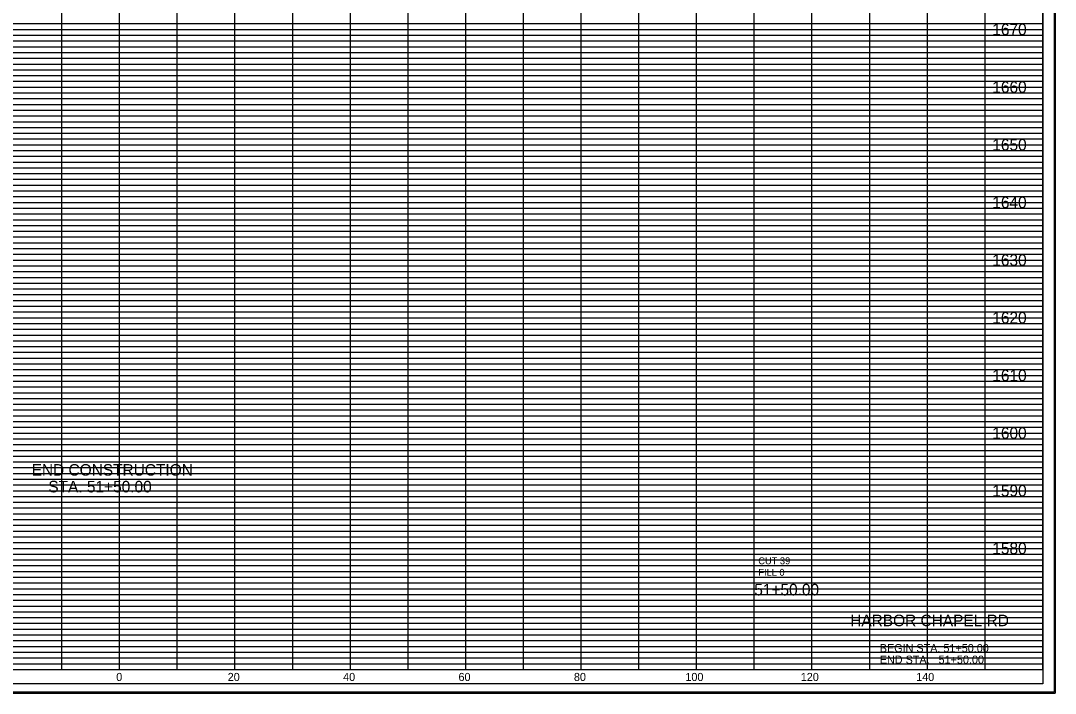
# Model space of a CAD drawing. Extents: x 980 to 1324, y 978 to 1767.
# Drawn here: x 1142.9 to 1322.2, y 1265.9 to 1382.5 of the extents above; entities that cross this region are included whole.
import ezdxf

# ---------------------------------------------------------------- set-up
doc = ezdxf.new("R2010")
doc.units = 0
for name, color, linetype in [('DESIGN - SHEET - Corner Text', 7, 'Continuous'), ('DESIGN - SHEET - Light Grid', 7, 'Continuous'), ('DESIGN - SHEET - Linework', 7, 'Continuous'), ('DESIGN - SHEET - Plot Shape', 7, 'Continuous'), ('DESIGN - TYPICAL - Finished Grade and Subgrade', 7, 'Continuous'), ('DESIGN - TYPICAL - Text', 7, 'Continuous')]:
    doc.layers.add(name, color=color, linetype=linetype)

# ---------------------------------------------------------------- blocks, each defined once
blk = doc.blocks.new('XSTSHT')
at = {"layer": 'DESIGN - SHEET - Light Grid'}
for p, q in [((8, 11.2), (16, 11.2)), ((16, 11.2), (24, 11.2)), ((24, 11.2), (32, 11.2)), ((8, 11.1), (16, 11.1)), ((16, 11.1), (24, 11.1)), ((24, 11.1), (32, 11.1)), ((8, 10.9), (16, 10.9)), ((8, 10.8), (16, 10.8)), ((16, 10.9), (24, 10.9)), ((16, 10.8), (24, 10.8)), ((24, 10.9), (32, 10.9)), ((24, 10.8), (32, 10.8)), ((8, 10.7), (16, 10.7)), ((8, 10.6), (16, 10.6)), ((16, 10.7), (24, 10.7)), ((16, 10.6), (24, 10.6)), ((24, 10.7), (32, 10.7)), ((24, 10.6), (32, 10.6)), ((8, 10.5), (16, 10.5)), ((8, 10.4), (16, 10.4)), ((16, 10.5), (24, 10.5)), ((16, 10.4), (24, 10.4)), ((24, 10.5), (32, 10.5)), ((24, 10.4), (32, 10.4)), ((8, 10.3), (16, 10.3)), ((16, 10.3), (24, 10.3)), ((24, 10.3), (32, 10.3)), ((8, 10.2), (16, 10.2)), ((8, 10.1), (16, 10.1)), ((16, 10.2), (24, 10.2)), ((16, 10.1), (24, 10.1)), ((24, 10.2), (32, 10.2)), ((24, 10.1), (32, 10.1)), ((8, 9.9), (16, 9.9)), ((16, 9.9), (24, 9.9)), ((24, 9.9), (32, 9.9)), ((8, 9.8), (16, 9.8)), ((8, 9.7), (16, 9.7)), ((16, 9.8), (24, 9.8)), ((16, 9.7), (24, 9.7)), ((24, 9.8), (32, 9.8)), ((24, 9.7), (32, 9.7)), ((8, 9.6), (16, 9.6)), ((16, 9.6), (24, 9.6)), ((24, 9.6), (32, 9.6)), ((8, 9.5), (16, 9.5)), ((8, 9.4), (16, 9.4)), ((16, 9.5), (24, 9.5)), ((16, 9.4), (24, 9.4)), ((24, 9.5), (32, 9.5)), ((24, 9.4), (32, 9.4)), ((8, 9.3), (16, 9.3)), ((8, 9.2), (16, 9.2)), ((16, 9.3), (24, 9.3)), ((16, 9.2), (24, 9.2)), ((24, 9.3), (32, 9.3)), ((24, 9.2), (32, 9.2)), ((8, 9.1), (16, 9.1)), ((16, 9.1), (24, 9.1)), ((24, 9.1), (32, 9.1)), ((8, 8.9), (16, 8.9)), ((8, 8.8), (16, 8.8)), ((16, 8.9), (24, 8.9)), ((16, 8.8), (24, 8.8)), ((24, 8.9), (32, 8.9)), ((24, 8.8), (32, 8.8)), ((8, 8.7), (16, 8.7)), ((16, 8.7), (24, 8.7)), ((24, 8.7), (32, 8.7)), ((8, 8.6), (16, 8.6)), ((8, 8.5), (16, 8.5)), ((16, 8.6), (24, 8.6)), ((16, 8.5), (24, 8.5)), ((24, 8.6), (32, 8.6)), ((24, 8.5), (32, 8.5)), ((8, 8.4), (16, 8.4)), ((8, 8.3), (16, 8.3)), ((16, 8.4), (24, 8.4)), ((16, 8.3), (24, 8.3)), ((24, 8.4), (32, 8.4)), ((24, 8.3), (32, 8.3)), ((8, 8.2), (16, 8.2)), ((8, 8.1), (16, 8.1)), ((16, 8.2), (24, 8.2)), ((16, 8.1), (24, 8.1)), ((24, 8.2), (32, 8.2)), ((24, 8.1), (32, 8.1)), ((8, 7.9), (16, 7.9)), ((16, 7.9), (24, 7.9)), ((24, 7.9), (32, 7.9)), ((8, 7.8), (16, 7.8)), ((16, 7.8), (24, 7.8)), ((24, 7.8), (32, 7.8)), ((8, 7.7), (16, 7.7)), ((8, 7.6), (16, 7.6)), ((16, 7.7), (24, 7.7)), ((16, 7.6), (24, 7.6)), ((24, 7.7), (32, 7.7)), ((24, 7.6), (32, 7.6)), ((8, 7.5), (16, 7.5)), ((8, 7.4), (16, 7.4)), ((16, 7.5), (24, 7.5)), ((16, 7.4), (24, 7.4)), ((24, 7.5), (32, 7.5)), ((24, 7.4), (32, 7.4)), ((8, 7.3), (16, 7.3)), ((8, 7.2), (16, 7.2)), ((16, 7.3), (24, 7.3)), ((16, 7.2), (24, 7.2)), ((24, 7.3), (32, 7.3)), ((24, 7.2), (32, 7.2)), ((8, 7.1), (16, 7.1)), ((16, 7.1), (24, 7.1)), ((24, 7.1), (32, 7.1)), ((8, 6.9), (16, 6.9)), ((16, 6.9), (24, 6.9)), ((24, 6.9), (32, 6.9)), ((8, 6.8), (16, 6.8)), ((8, 6.7), (16, 6.7)), ((16, 6.8), (24, 6.8)), ((16, 6.7), (24, 6.7)), ((24, 6.8), (32, 6.8)), ((24, 6.7), (32, 6.7)), ((8, 6.6), (16, 6.6)), ((8, 6.5), (16, 6.5)), ((16, 6.6), (24, 6.6)), ((16, 6.5), (24, 6.5)), ((24, 6.6), (32, 6.6)), ((24, 6.5), (32, 6.5)), ((8, 6.4), (16, 6.4)), ((8, 6.3), (16, 6.3)), ((16, 6.4), (24, 6.4)), ((16, 6.3), (24, 6.3)), ((24, 6.4), (32, 6.4)), ((24, 6.3), (32, 6.3)), ((8, 6.2), (16, 6.2)), ((8, 6.1), (16, 6.1)), ((16, 6.2), (24, 6.2)), ((16, 6.1), (24, 6.1)), ((24, 6.2), (32, 6.2)), ((24, 6.1), (32, 6.1)), ((8, 5.9), (16, 5.9)), ((8, 5.8), (16, 5.8)), ((16, 5.9), (24, 5.9)), ((16, 5.8), (24, 5.8)), ((24, 5.9), (32, 5.9)), ((24, 5.8), (32, 5.8)), ((8, 5.7), (16, 5.7)), ((8, 5.6), (16, 5.6)), ((16, 5.7), (24, 5.7)), ((16, 5.6), (24, 5.6)), ((24, 5.7), (32, 5.7)), ((24, 5.6), (32, 5.6)), ((8, 5.5), (16, 5.5)), ((8, 5.4), (16, 5.4)), ((16, 5.5), (24, 5.5)), ((16, 5.4), (24, 5.4)), ((24, 5.5), (32, 5.5)), ((24, 5.4), (32, 5.4)), ((8, 5.3), (16, 5.3)), ((8, 5.2), (16, 5.2)), ((16, 5.3), (24, 5.3)), ((16, 5.2), (24, 5.2)), ((24, 5.3), (32, 5.3)), ((24, 5.2), (32, 5.2)), ((8, 5.1), (16, 5.1)), ((16, 5.1), (24, 5.1)), ((24, 5.1), (32, 5.1)), ((8, 4.9), (16, 4.9)), ((16, 4.9), (24, 4.9)), ((24, 4.9), (32, 4.9)), ((8, 4.8), (16, 4.8)), ((8, 4.7), (16, 4.7)), ((16, 4.8), (24, 4.8)), ((16, 4.7), (24, 4.7)), ((24, 4.8), (32, 4.8)), ((24, 4.7), (32, 4.7)), ((8, 4.6), (16, 4.6)), ((8, 4.5), (16, 4.5)), ((16, 4.6), (24, 4.6)), ((16, 4.5), (24, 4.5)), ((24, 4.6), (32, 4.6)), ((24, 4.5), (32, 4.5)), ((8, 4.4), (16, 4.4)), ((16, 4.4), (24, 4.4)), ((24, 4.4), (32, 4.4)), ((8, 4.3), (16, 4.3)), ((8, 4.2), (16, 4.2)), ((16, 4.3), (24, 4.3)), ((16, 4.2), (24, 4.2)), ((24, 4.3), (32, 4.3)), ((24, 4.2), (32, 4.2)), ((8, 4.1), (16, 4.1)), ((16, 4.1), (24, 4.1)), ((24, 4.1), (32, 4.1)), ((8, 3.9), (16, 3.9)), ((8, 3.8), (16, 3.8)), ((16, 3.9), (24, 3.9)), ((16, 3.8), (24, 3.8)), ((24, 3.9), (32, 3.9)), ((24, 3.8), (32, 3.8)), ((8, 3.7), (16, 3.7)), ((8, 3.6), (16, 3.6)), ((16, 3.7), (24, 3.7)), ((16, 3.6), (24, 3.6)), ((24, 3.7), (32, 3.7)), ((24, 3.6), (32, 3.6)), ((8, 3.5), (16, 3.5)), ((16, 3.5), (24, 3.5)), ((24, 3.5), (32, 3.5)), ((8, 3.4), (16, 3.4)), ((8, 3.3), (16, 3.3)), ((16, 3.4), (24, 3.4)), ((16, 3.3), (24, 3.3)), ((24, 3.4), (32, 3.4)), ((24, 3.3), (32, 3.3)), ((8, 3.2), (16, 3.2)), ((8, 3.1), (16, 3.1)), ((16, 3.2), (24, 3.2)), ((16, 3.1), (24, 3.1)), ((24, 3.2), (32, 3.2)), ((24, 3.1), (32, 3.1)), ((8, 2.9), (16, 2.9)), ((16, 2.9), (24, 2.9)), ((24, 2.9), (32, 2.9)), ((8, 2.8), (16, 2.8)), ((8, 2.7), (16, 2.7)), ((16, 2.8), (24, 2.8)), ((16, 2.7), (24, 2.7)), ((24, 2.8), (32, 2.8)), ((24, 2.7), (32, 2.7)), ((8, 2.6), (16, 2.6)), ((16, 2.6), (24, 2.6)), ((24, 2.6), (32, 2.6)), ((8, 2.5), (16, 2.5)), ((8, 2.4), (16, 2.4)), ((16, 2.5), (24, 2.5)), ((16, 2.4), (24, 2.4)), ((24, 2.5), (32, 2.5)), ((24, 2.4), (32, 2.4)), ((8, 2.3), (16, 2.3)), ((8, 2.2), (16, 2.2)), ((16, 2.3), (24, 2.3)), ((16, 2.2), (24, 2.2)), ((24, 2.3), (32, 2.3)), ((24, 2.2), (32, 2.2)), ((8, 2.1), (16, 2.1)), ((16, 2.1), (24, 2.1)), ((24, 2.1), (32, 2.1)), ((8, 1.9), (16, 1.9)), ((8, 1.8), (16, 1.8)), ((16, 1.9), (24, 1.9)), ((16, 1.8), (24, 1.8)), ((24, 1.9), (32, 1.9)), ((24, 1.8), (32, 1.8)), ((8, 1.7), (16, 1.7)), ((16, 1.7), (24, 1.7)), ((24, 1.7), (32, 1.7)), ((8, 1.6), (16, 1.6)), ((8, 1.5), (16, 1.5)), ((16, 1.6), (24, 1.6)), ((16, 1.5), (24, 1.5)), ((24, 1.6), (32, 1.6)), ((24, 1.5), (32, 1.5)), ((8, 1.4), (16, 1.4)), ((8, 1.3), (16, 1.3)), ((16, 1.4), (24, 1.4)), ((16, 1.3), (24, 1.3)), ((24, 1.4), (32, 1.4)), ((24, 1.3), (32, 1.3)), ((8, 1.2), (16, 1.2)), ((8, 1.1), (16, 1.1)), ((16, 1.2), (24, 1.2)), ((16, 1.1), (24, 1.1)), ((24, 1.2), (32, 1.2)), ((24, 1.1), (32, 1.1)), ((8, 0.9), (16, 0.9)), ((16, 0.9), (24, 0.9)), ((24, 0.9), (32, 0.9)), ((8, 0.8), (16, 0.8)), ((16, 0.8), (24, 0.8)), ((24, 0.8), (32, 0.8)), ((8, 0.7), (16, 0.7)), ((8, 0.6), (16, 0.6)), ((16, 0.7), (24, 0.7)), ((16, 0.6), (24, 0.6)), ((24, 0.7), (32, 0.7)), ((24, 0.6), (32, 0.6)), ((8, 0.5), (16, 0.5)), ((8, 0.4), (16, 0.4)), ((16, 0.5), (24, 0.5)), ((16, 0.4), (24, 0.4)), ((24, 0.5), (32, 0.5)), ((24, 0.4), (32, 0.4)), ((8, 0.3), (16, 0.3)), ((8, 0.2), (16, 0.2)), ((16, 0.3), (24, 0.3)), ((16, 0.2), (24, 0.2)), ((24, 0.3), (32, 0.3)), ((24, 0.2), (32, 0.2)), ((8, 0.1), (16, 0.1)), ((16, 0.1), (24, 0.1)), ((24, 0.1), (32, 0.1))]:
    blk.add_line(p, q, dxfattribs=at)
at = {"layer": 'DESIGN - SHEET - Linework'}
for p, q in [((32.217, 21.414), (32.217, -0.414)), ((15, 0), (15, 21)), ((16, 0), (16, 21)), ((17, 0), (17, 21)), ((18, 0), (18, 21)), ((19, 0), (19, 21)), ((20, 0), (20, 21)), ((21, 0), (21, 21)), ((22, 0), (22, 21)), ((23, 0), (23, 21)), ((24, 0), (24, 21)), ((25, 0), (25, 21)), ((26, 0), (26, 21)), ((27, 0), (27, 21)), ((28, 0), (28, 20)), ((29, 0), (29, 20)), ((30, 0), (30, 20)), ((31, 0), (31, 20)), ((0, 11), (32, 11)), ((0, 10), (32, 10)), ((0, 9), (32, 9)), ((0, 8), (32, 8)), ((0, 7), (32, 7)), ((0, 6), (32, 6)), ((0, 5), (32, 5)), ((0, 4), (32, 4)), ((0, 3), (32, 3)), ((0, 2), (32, 2)), ((0, 1), (32, 1)), ((-1.823, -0.414), (32.217, -0.414))]:
    blk.add_line(p, q, dxfattribs=at)
blk.add_lwpolyline([(0, 21), (0, 0), (32, 0), (32, 21), (0, 21)], dxfattribs=at)
at = {"layer": 'DESIGN - SHEET - Plot Shape'}
for points in [[(-1.803, 21.394), (32.197, 21.394), (32.197, -0.394), (-1.803, -0.394)], [(-0.85, 21), (32, 21), (32, -0.25), (-0.85, -0.25)]]:
    blk.add_lwpolyline(points, close=True, dxfattribs=at)

msp = doc.modelspace()

# ---------------------------------------------------------------- linework, layer by layer
at = {"layer": 'DESIGN - SHEET - Plot Shape'}
msp.add_lwpolyline([(991.5, 1480), (1320, 1480), (1320, 1267.5), (991.5, 1267.5)], close=True, dxfattribs=at)

# ---------------------------------------------------------------- block references
at = {"layer": 'DESIGN - TYPICAL - Finished Grade and Subgrade', "xscale": 10, "yscale": 10}
msp.add_blockref('XSTSHT', (1000, 1270), dxfattribs=at)

# ---------------------------------------------------------------- texts
at = {"layer": 'DESIGN - SHEET - Corner Text'}
for s, height, p in [('1670', 2, (1311.25, 1380)), ('1660', 2, (1311.25, 1370)), ('1650', 2, (1311.25, 1360)), ('1640', 2, (1311.25, 1350)), ('1630', 2, (1311.25, 1340)), ('1620', 2, (1311.25, 1330)), ('1610', 2, (1311.25, 1320)), ('1600', 2, (1311.25, 1310)), ('1590', 2, (1311.25, 1300)), ('1580', 2, (1311.25, 1290)), ('HARBOR CHAPEL RD', 2, (1286.63, 1277.5)), ('BEGIN STA. 51+50.00', 1.4, (1291.75, 1273)), ('END STA.   51+50.00', 1.4, (1291.75, 1271)), ('0', 1.4, (1159.42, 1268)), ('0', 1.4, (1159.42, 1268)), ('20', 1.4, (1178.74, 1268)), ('40', 1.4, (1198.74, 1268)), ('60', 1.4, (1218.74, 1268)), ('80', 1.4, (1238.74, 1268)), ('100', 1.4, (1258.06, 1268)), ('120', 1.4, (1278.06, 1268)), ('140', 1.4, (1298.06, 1268))]:
    msp.add_text(s, height=height, dxfattribs=at).set_placement(p)
at = {"layer": 'DESIGN - TYPICAL - Text'}
for s, height, p in [('END CONSTRUCTION', 2, (1144.76, 1303.61)), ('STA. 51+50.00', 2, (1147.65, 1300.71)), ('CUT 39', 1.2, (1270.7, 1288.24)), ('FILL 0', 1.2, (1270.7, 1286.24)), ('51+50.00', 2, (1270, 1282.84))]:
    msp.add_text(s, height=height, dxfattribs=at).set_placement(p)

doc.saveas('drawing.dxf')
